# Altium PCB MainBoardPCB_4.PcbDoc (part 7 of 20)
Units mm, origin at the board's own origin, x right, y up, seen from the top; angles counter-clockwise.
Board outline 333.63 x 349.38 mm, 16 copper layers (L1, L2 (GND), L3 (Sign), L4 (GND), L5 (Sign), L6 (PWR/GND), L7(PWR/GND), L8 (Plane_GND), L9 (PWR/GND), L10 (PWR/GND), L11 (PWR/GND), L12 (Sign), L13 (GND), L14 (Sign), L15 (GND), L16), stack 2.502 mm thick; 2205 components, 1648 nets, 8314 pads, 3172 vias.
Unrouted connection lines stored in the file: 5141.
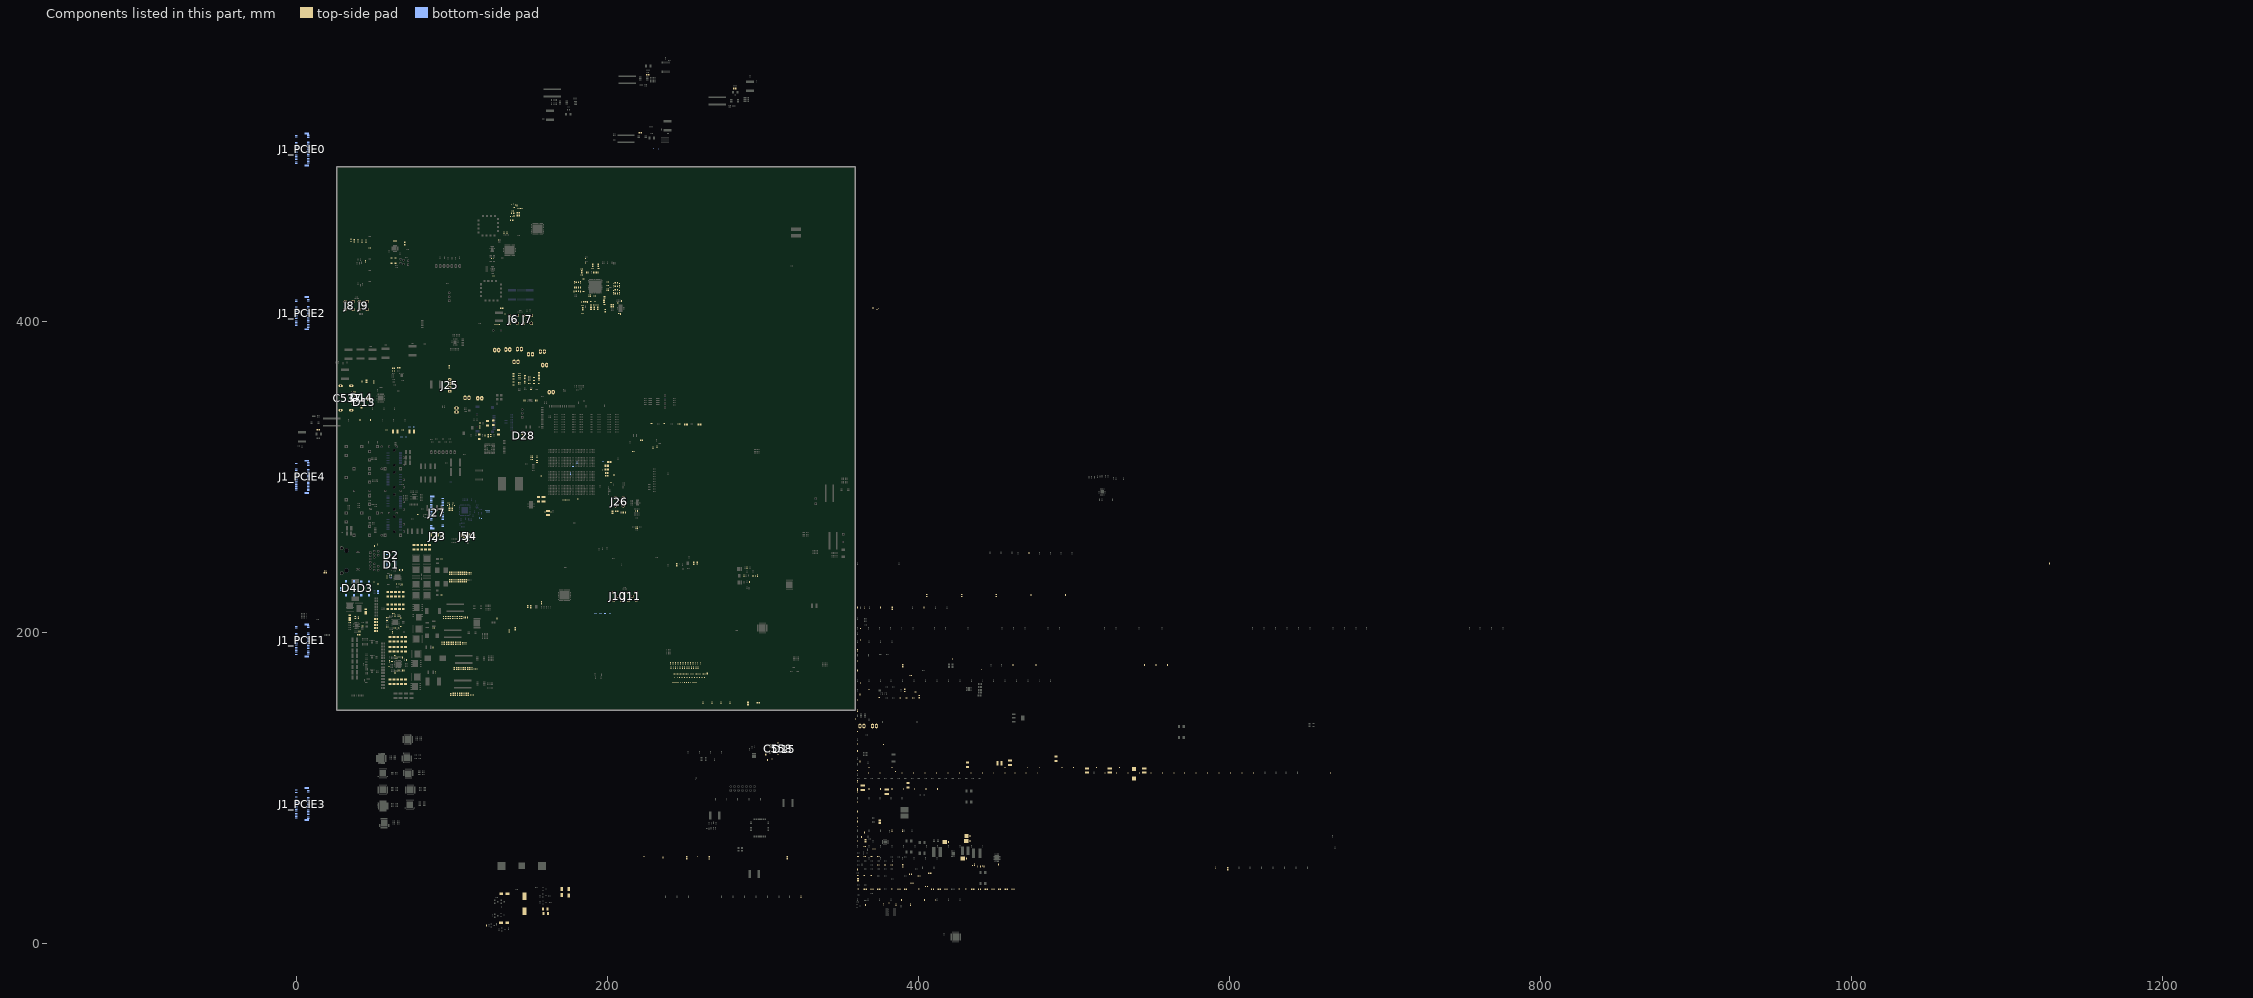
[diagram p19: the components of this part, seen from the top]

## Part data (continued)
C46: library part Capacitor, "Multilayer Ceramic Capacitors MLCC - SMD/SMT 200pF 50V NPO 5%", Case Code (Imperial)=0402, Case Code (Metric)=1005, Dielectric=C0G, Manufacturer=Yageo, Manufacturer Part Number=CC0402JRNPO9BN201, Max Operating Temperature=125°C, Min Operating Temperature=-55°C, Supplier Part Number 1=311-1664-1-ND, Tolerance=5%, Voltage Rating=50V
C53 C54 C326 C327 C328 C329: library part Capacitor, Case/Package=0402, Dielectric=X5R, Dielectric Material=Ceramic, Manufacturer=KEMET, Manufacturer Part Number=C0402C105K9PACTU, Max Operating Temperature=85°C, Min Operating Temperature=-55°C, Package Quantity=1, Supplier Part Number 1=399-4873-6-ND, Tolerance=10%, Voltage=6.3V
C55 C56 C57 C59 C60 C61 C65 C66 C71 C72 C73 C84 C85 C94 C95: library part Capacitor, "SMT Capacitor", Part Number=GRM033R61C104ME84D, Supplier Part Number 1=490-9986-1-ND
C58 C62 C69 C74 C87 C98: library part Capacitor, "SMT Capacitor", Part Number=AMK105CBJ106MV-F, Supplier Part Number 1=587-3237-1-ND
C63 C64 C67 C70 C75 C76 C77 C81 C82 C83 C88 C89 C90 C91 C92 C93 C96 C99 C100 C103 C104 C107 C108 C124 C125 C141 C142 C145 C146 C162 C163 C179 C336 C337 C338 C578 C579 C583 C590: library part Capacitor, "CAP CER 0.1UF 50V X5R 0402", Case Code (Imperial)=0402, Case Code (Metric)=1005, Dielectric=X5R, Dielectric Material=Ceramic, Manufacturer=Murata, Manufacturer Part Number=GRM155R61H104KE14D, Max Operating Temperature=85°C, Min Operating Temperature=-55°C, Package Quantity=10000, Supplier Part Number 1=490-10697-1-ND, Tolerance=10%, Voltage=50V
C68 C86 C97 C111 C112 C113 C114 C115 C116 C117 C118 C119 C120 C121 C122 C123 C149 C150 C151 C152 C153 C154 C155 C156 C157 C158 C159 C160 C161 C166 C167 C168 C169 C170 C171 C172 C173 C174 C175 C176 C177 C178 C333 C344 C573 C577: library part Capacitor, "Cap Ceramic 0.01uF 16V X5R 10% SMD 0201 85C Paper T/R", Case Code (Imperial)=0201, Case Code (Metric)=0603, Dielectric=X5R, Manufacturer=Yageo, Manufacturer Part Number=CC0201KRX5R7BB103, Max Operating Temperature=85°C, Min Operating Temperature=-55°C, Supplier Part Number 1=311-1596-1-ND, Tolerance=10%, Voltage Rating=16V
C78 C79 C80 C101 C102 C105 C106 C109 C110 C126 C127 C143 C144 C147 C148 C164 C165 C180 C591: library part Capacitor, "CAP CER 10UF 10V X5R 0402", Case Code (Imperial)=0402, Case Code (Metric)=1005, Manufacturer=Samsung, Manufacturer Part Number=CL05A106MP8NUB8, Max Operating Temperature=85°C, Min Operating Temperature=-55°C, Supplier Part Number 1=1276-6830-1-ND, Tolerance=20%, Voltage Rating=10V
C128 C129 C130 C131 C132 C133 C134 C135 C136 C137 C138 C139 C140 C181 C182 C183 C184 C185 C186 C187 C188 C189 C190 C191 C192 C193 C194 C195 C196 C197 C198 C199 C200 C201 C202 C203 C204 C205 C206: library part Capacitor, "CAP CER 1UF 10V X5R 0402", Case Code (Imperial)=0402, Case Code (Metric)=1005, Dielectric=X5R, Manufacturer=Yageo, Manufacturer Part Number=CC0402KRX5R6BB105, Max Operating Temperature=85°C, Min Operating Temperature=-55°C, Package Quantity=1, Supplier Part Number 1=311-1439-1-ND, Tolerance=10%, Voltage Rating=10V
C207 C209: library part Capacitor, Case/Package=0402, Case Code (Metric)=1005, Dielectric=X7R, Manufacturer=Murata, Manufacturer Part Number=GRM155R71E104KE14J, Max Operating Temperature=125°C, Min Operating Temperature=-55°C, Package Quantity=50000, Supplier Part Number 1=490-14603-1-ND, Tolerance=10%, Voltage Rating=25V
C208 C210: library part Capacitor, Case/Package=1210, Case Code (Metric)=3225, Dielectric=X5R, Manufacturer=Samsung, Manufacturer Part Number=CL32A226KAJNNNE, Max Operating Temperature=85°C, Min Operating Temperature=-55°C, Package Quantity=1, Supplier Part Number 1=1276-1101-1-ND, Tolerance=10%, Voltage=25V
C223 C228 C233 C238 C247 C252 C257 C262 C550 C552 C554 C568 C569 C570: library part Capacitor, "0402 10 V 4.7 uF ±20% Tolerance X5R Multilayer Ceramic Chip Capacitor", Case Code (Imperial)=0402, Case Code (Metric)=1005, Manufacturer=Murata, Manufacturer Part Number=GRM155R61A475MEAAD, Max Operating Temperature=85°C, Min Operating Temperature=-55°C, Supplier Part Number 1=490-14306-1-ND, Tolerance=20%, Voltage Rating=10V
C224 C225 C229 C230 C234 C235 C239 C240 C248 C249 C253 C254 C258 C259 C263 C264: library part Capacitor, "Cap Ceramic 0.47uF 10V X5R 10% SMD 0402 85C Paper T/R", Case Code (Imperial)=0402, Case Code (Metric)=1005, Dielectric=X5R, Manufacturer=Samsung, Manufacturer Part Number=CL05A474KP5NNNC, Max Operating Temperature=85°C, Min Operating Temperature=-55°C, Supplier Part Number 1=1276-1173-1-ND, Tolerance=10%, Voltage Rating=10V
C226 C227 C231 C232 C236 C237 C241 C242 C250 C251 C255 C256 C260 C261 C265 C266: library part Capacitor, "KEMET - C0402C683K4RACTU - CAP, 0.068µF, 16V, 10%, X7R, 0402", Case Code (Imperial)=0402, Case Code (Metric)=1005, Dielectric=X7R, Dielectric Material=Ceramic, Manufacturer=KEMET, Manufacturer Part Number=C0402C683K4RACTU, Max Operating Temperature=125°C, Min Operating Temperature=-55°C, Package Quantity=1, Supplier Part Number 1=399-4904-1-ND, Tolerance=10%, Voltage=16V
C267 C269 C271 C274 C279 C281 C283 C286 C291 C293 C295 C298: library part Capacitor, "CAP CER 0.1UF 16V X5R 0201", Case Code (Metric)=0603, Case/Package=0201, Dielectric=X5R, Manufacturer=Murata, Manufacturer Part Number=GRM033R61C104ME84D, Max Operating Temperature=85°C, Min Operating Temperature=-55°C, Package Quantity=15000, Supplier Part Number 1=490-9986-1-ND, Tolerance=20%, Voltage Rating=16V
C268 C270 C272 C275 C280 C282 C284 C287 C292 C294 C296 C299 C629: library part Capacitor, "CAP CER 0.1UF 16V X5R 0201", Case Code (Imperial)=0201, Case Code (Metric)=0603, Dielectric=X5R, Manufacturer=Murata, Manufacturer Part Number=GRM033R61C104ME84D, Max Operating Temperature=85°C, Min Operating Temperature=-55°C, Package Quantity=15000, Supplier Part Number 1=490-9986-1-ND, Tolerance=20%, Voltage Rating=16V
C273 C276 C277 C278 C285 C288 C289 C290 C297 C300 C301 C302: library part Capacitor, "CAP CER 10000PF 16V X7R 0201", Dielectric=X7R, Manufacturer=Murata, Manufacturer Part Number=GRM033R71C103KE14D, Supplier Part Number 1=490-14453-1-ND, Tolerance=10%, Voltage Rating (DC)=16V
C303_I2C_Bridge C303_I2C_Bridge_2 C303_I2C_Bridge_3 C406 C418 C447 C459 C517 C519 C521 C545 C546 C547 C566_5V_to_3V3_for_FTDI C623 C649 C651 C653 C654 C677 C715 C716 C717 C718: library part Capacitor, Case/Package=0402, Case Code (Metric)=1005, Dielectric=X5R, Insulation Resistance=10GR, Manufacturer=Yageo, Manufacturer Part Number=CC0402KRX5R6BB104, Max Operating Temperature=85°C, Min Operating Temperature=-55°C, Package Quantity=1, Supplier Part Number 1=311-1336-1-ND, Tolerance=10%, Voltage Rating=10V
C304 C305 C306 C307: library part Capacitor, "SMT Capacitor", Part Number=CL10A475KO8NNNC, Supplier Part Number 1=1276-1784-2-ND
C308 C354 C355 C606 C607 C610 C611 C613 C614 C615 C617 C618 C619 C620 C621 C622: library part Capacitor, "SMT Capacitor", Part Number=CL10A475KQ8NNNC, Supplier Part Number 1=1276-1045-1-ND
C309_U_Pomiar_pradu_napiecia_1 C309_U_Pomiar_pradu_napiecia_2 C309_U_Pomiar_pradu_napiecia_3 C309_U_Pomiar_pradu_napiecia_4 C309_U_Pomiar_pradu_napiecia_5 C309_U_Pomiar_pradu_napiecia_6 C309_U_Pomiar_pradu_napiecia_7 C309_U_Pomiar_pradu_napiecia_8 C309_U_Pomiar_pradu_napiecia_9 C309_U_Pomiar_pradu_napiecia_10 C309_U_Pomiar_pradu_napiecia_11 C310 C585 C711 C712: library part Capacitor, "CAP CER 0.1UF 50V X5R 0402", Case/Package=0402, Case Code (Metric)=1005, Dielectric=X5R, Dielectric Material=Ceramic, Manufacturer=Murata, Manufacturer Part Number=GRM155R61H104KE14D, Max Operating Temperature=85°C, Min Operating Temperature=-55°C, Package Quantity=10000, Supplier Part Number 1=490-10697-1-ND, Tolerance=10%, Voltage=50V
C311_I2C_Expander1 C311_I2C_Expander2 C311_I2C_Expander3 C311_I2C_Expander? C311_I2C_Expander_10 C311_I2C_Expander_11 C311_I2C_Expander_12 C311_I2C_Expander_13 C311_I2C_Expander_14 C311_I2C_Expander_15 C311_I2C_Expander_16 C544 C700 C720 C721 C722 C723: library part Capacitor, "MURATA - GRT155R61E105KE01D - SMD Multilayer Ceramic Capacitor, 1 µF, 25 V, 0402 [1005 Metric], ± 10%, X5R, GRT Series - SMD Multilayer Ceramic Capacitor, 1 µF, 25 V, 0402 [1005 Metric], ± 10%, X5R, GRT Series", Case/Package=0402, Case Code (Metric)=1005, Dielectric=X5R, Manufacturer=Murata, Manufacturer Part Number=GRT155R61E105KE01D, Max Operating Temperature=85°C, Min Operating Temperature=-55°C, Ratings=AEC-Q200, Supplier Part Number 1=490-12263-1-ND, Tolerance=10%, Voltage Rating=25V
C320: library part Capacitor, Case/Package=0402, Case Code (Metric)=1005, Dielectric=X7R, Dielectric Material=Ceramic, Manufacturer=KEMET, Manufacturer Part Number=C0402C103K8RACAUTO, Max Operating Temperature=125°C, Min Operating Temperature=-55°C, Package Quantity=1, Ratings=AEC-Q200, Supplier Part Number 1=399-6827-1-ND, Tolerance=10%, Voltage Rating=10V
C321: library part Capacitor, Case/Package=0603, Case Code (Metric)=1608, Manufacturer="Wurth Electronics", Manufacturer Part Number=885012006016, Max Operating Temperature=125°C, Min Operating Temperature=-55°C, Supplier Part Number 1=732-7759-1-ND, Tolerance=5%, Voltage Rating=10V
C322 C323: library part Capacitor, Case/Package=0402, Case Code (Metric)=1005, Dielectric=C0G, Dielectric Material=Ceramic, Manufacturer=KEMET, Manufacturer Part Number=C0402C270K5GACTU, Max Operating Temperature=125°C, Min Operating Temperature=-55°C, Package Quantity=1, Supplier Part Number 1=399-8960-1-ND, Tolerance=10%, Voltage Rating=50V
C324: library part Capacitor, Case/Package=0805, Case Code (Metric)=2012, Manufacturer=Samsung, Manufacturer Part Number=CL21A106KQCLRNC, Max Operating Temperature=85°C, Min Operating Temperature=-55°C, Package Quantity=1, Supplier Part Number 1=1276-2405-1-ND, Tolerance=10%, Voltage Rating=6.3V
C325 C330 C334 C335 C342 C343 C593 C594: library part Capacitor, Case Code (Imperial)=0402, Case Code (Metric)=1005, Dielectric=X7R, Dielectric Material=Ceramic, Insulation Resistance=10GR, Manufacturer=Murata, Manufacturer Part Number=GRM155R71C104KA88D, Max Operating Temperature=125°C, Min Operating Temperature=-55°C, Package Quantity=1, Supplier Part Number 1=490-3261-6-ND, Tolerance=10%, Voltage=16V
C331 C332 C395 C398 C408 C420 C436 C439 C449 C461 C522 C538 C559 C733 C734: library part Capacitor, Case/Package=0402, Case Code (Metric)=1005, Dielectric=X5R, Manufacturer=Yageo, Manufacturer Part Number=CC0402KRX5R6BB105, Max Operating Temperature=85°C, Min Operating Temperature=-55°C, Package Quantity=1, Supplier Part Number 1=311-1439-1-ND, Tolerance=10%, Voltage Rating=10V
C339: library part Capacitor, Case Code (Imperial)=0805, Case Code (Metric)=2012, Manufacturer=Samsung, Manufacturer Part Number=CL21A106KQCLRNC, Max Operating Temperature=85°C, Min Operating Temperature=-55°C, Package Quantity=1, Supplier Part Number 1=1276-2405-1-ND, Tolerance=10%, Voltage Rating=6.3V
C341 C479 C482 C483 C484 C540 C541 C542 C543 C728 C729 C732 C735 C790: library part Capacitor, Case/Package=0402, Case Code (Metric)=1005, Dielectric=X7R, Dielectric Material=Ceramic, Insulation Resistance=10GR, Manufacturer=Murata, Manufacturer Part Number=GRM155R71C104KA88D, Max Operating Temperature=125°C, Min Operating Temperature=-55°C, Package Quantity=1, Supplier Part Number 1=490-3261-6-ND, Tolerance=10%, Voltage=16V
C345 C349 C535 C536: library part Capacitor, Case Code (Imperial)=0402, Case Code (Metric)=1005, Dielectric=C0G, Manufacturer="Kyocera AVX", Manufacturer Part Number=04025A220JAT2A, Max Operating Temperature=125°C, Min Operating Temperature=-55°C, Package Quantity=1, Supplier Part Number 1=478-1074-1-ND, Temperature Coefficient=30ppm/°C, Tolerance=5%, Voltage=50V
C346 C350 C713: library part Capacitor, Case Code (Imperial)=0402, Case Code (Metric)=1005, Dielectric=X5R, Manufacturer=Multicomp, Manufacturer Part Number=MC0402X104K160CT, Max Operating Temperature=85°C, Min Operating Temperature=-55°C, Supplier Part Number 1=2310529, Tolerance=10%, Voltage Rating=16V
C347 C348 C352 C353 C391 C392 C396 C397 C432 C433 C437 C438: library part Capacitor, Case/Package=1206, Case Code (Metric)=3216, Dielectric=X7R, Manufacturer 1=Murata, Manufacturer Part Number 1=GRM31CR71E106MA12L, Max Operating Temperature=125°C, Min Operating Temperature=-55°C, Package Quantity=1, Supplier Part Number 1=490-6519-1-ND, Tolerance=20%, Voltage=25V
C351 C356 C361 C379 C680: library part Capacitor, Case Code (Imperial)=0402, Case Code (Metric)=1005, Dielectric=X5R, Manufacturer=Yageo, Manufacturer Part Number=CC0402KRX5R6BB105, Max Operating Temperature=85°C, Min Operating Temperature=-55°C, Package Quantity=1, Supplier Part Number 1=311-1439-1-ND, Tolerance=10%, Voltage Rating=10V
C357 C399 C440: library part Capacitor, Case/Package=0402, Case Code (Metric)=1005, Dielectric=X5R, Dielectric Material=Ceramic, Manufacturer 1=KEMET, Manufacturer Part Number 1=C0402C104M8PACTU, Max Operating Temperature=85°C, Min Operating Temperature=-55°C, Package Quantity=1, Supplier Part Number 1=399-7764-1-ND, Tolerance=20%, Voltage=10V
C358: library part Capacitor, "Cap Ceramic 1uF 10V X5R 10% SMD 0603 85C Paper T/R", Case Code (Imperial)=0603, Case Code (Metric)=1608, Dielectric=X5R, Manufacturer=Samsung, Manufacturer Part Number=CL10A105KP8NNNC, Max Operating Temperature=85°C, Min Operating Temperature=-55°C, Package Quantity=1, Supplier Part Number 1=1276-1182-1-ND, Tolerance=10%, Voltage=10V
C360 C378: library part Capacitor, Case Code (Imperial)=0402, Case Code (Metric)=1005, Dielectric=X5R, Manufacturer=Samsung, Manufacturer Part Number=CL05A474KP5NNNC, Max Operating Temperature=85°C, Min Operating Temperature=-55°C, Supplier Part Number 1=1276-1173-1-ND, Tolerance=10%, Voltage Rating=10V
C362 C380 C563_U_5V_to_3V31 C563_U_5V_to_3V32 C563_U_5V_to_3V33 C564_U_5V_to_3V31 C564_U_5V_to_3V32 C564_U_5V_to_3V33 C565_U_5V_to_3V31 C565_U_5V_to_3V32 C565_U_5V_to_3V33: library part Capacitor, Case Code (Imperial)=0603, Case Code (Metric)=1608, Dielectric=X5R, Manufacturer=Samsung, Manufacturer Part Number=CL10A475KP8NNNC, Max Operating Temperature=85°C, Min Operating Temperature=-55°C, Package Quantity=1, Supplier Part Number 1=1276-1044-1-ND, Tolerance=10%, Voltage Rating=10V
C363 C365 C367 C369 C381 C383 C385 C387 C572 C576 C598 C631: library part Capacitor, Case Code (Imperial)=0603, Case Code (Metric)=1608, Dielectric=X5R, Manufacturer=Murata, Manufacturer Part Number=GRM188R61A106KE69D, Max Operating Temperature=85°C, Min Operating Temperature=-55°C, Supplier Part Number 1=490-10474-1-ND, Tolerance=10%, Voltage=10V
C364 C366 C368 C370 C382 C384 C386 C388: library part Capacitor, Case Code (Imperial)=0603, Case Code (Metric)=1608, Dielectric=X5R, Manufacturer=Murata, Manufacturer Part Number=GRM188R61A226ME15D, Max Operating Temperature=85°C, Min Operating Temperature=-55°C, Package Quantity=4000, Supplier Part Number 1=490-10476-1-ND, Tolerance=20%, Voltage Rating=10V
C371 C372 C373 C374 C375 C376: library part Capacitor, "Cap Ceramic 10uF 25V X5R 10% SMD 1206 85C Embossed T/R", Case Code (Imperial)=1206, Case Code (Metric)=3216, Dielectric=X5R, Manufacturer=Samsung, Manufacturer Part Number=CL31A106KAHNNNE, Max Operating Temperature=85°C, Min Operating Temperature=-55°C, Supplier Part Number 1=1276-1075-1-ND, Tolerance=10%, Voltage=25V
C389 C393 C430 C434: library part Capacitor, Case/Package=0402, Case Code (Metric)=1005, Dielectric=C0G, Manufacturer="Kyocera AVX", Manufacturer Part Number=04025A220JAT2A, Max Operating Temperature=125°C, Min Operating Temperature=-55°C, Package Quantity=1, Supplier Part Number 1=478-1074-1-ND, Temperature Coefficient=30ppm/°C, Tolerance=5%, Voltage=50V
C390 C394 C431 C435 C658 C660 C662 C665 C666 C667 C668 C669 C670 C671 C673 C783 C785 C787 C789 C791 C792: library part Capacitor, Case/Package=0402, Case Code (Metric)=1005, Dielectric=X5R, Manufacturer=Multicomp, Manufacturer Part Number=MC0402X104K160CT, Max Operating Temperature=85°C, Min Operating Temperature=-55°C, Supplier Part Number 1=2310529, Tolerance=10%, Voltage Rating=16V
C400 C401 C402 C403 C404 C405 C441 C442 C443 C444 C445 C446: library part Capacitor, "Cap Ceramic 10uF 25V X5R 10% SMD 1206 85C Embossed T/R", Case/Package=1206, Case Code (Metric)=3216, Dielectric=X5R, Manufacturer=Samsung, Manufacturer Part Number=CL31A106KAHNNNE, Max Operating Temperature=85°C, Min Operating Temperature=-55°C, Supplier Part Number 1=1276-1075-1-ND, Tolerance=10%, Voltage=25V
C407 C419 C448 C460: library part Capacitor, Case/Package=0402, Case Code (Metric)=1005, Dielectric=X5R, Manufacturer=Samsung, Manufacturer Part Number=CL05A474KP5NNNC, Max Operating Temperature=85°C, Min Operating Temperature=-55°C, Supplier Part Number 1=1276-1173-1-ND, Tolerance=10%, Voltage Rating=10V
C409 C421 C450 C462 C515 C516 C523 C524 C539 C560 C563_5V_to_3V3_for_FTDI C564_5V_to_3V3_for_FTDI C565_5V_to_3V3_for_FTDI C659 C661: library part Capacitor, Case/Package=0603, Case Code (Metric)=1608, Dielectric=X5R, Manufacturer=Samsung, Manufacturer Part Number=CL10A475KP8NNNC, Max Operating Temperature=85°C, Min Operating Temperature=-55°C, Package Quantity=1, Supplier Part Number 1=1276-1044-1-ND, Tolerance=10%, Voltage Rating=10V
C410 C412 C414 C416 C422 C424 C426 C428 C451 C453 C455 C457 C463 C465 C467 C469 C705 C709: library part Capacitor, Case/Package=0603, Case Code (Metric)=1608, Dielectric=X5R, Manufacturer=Murata, Manufacturer Part Number=GRM188R61A106KE69D, Max Operating Temperature=85°C, Min Operating Temperature=-55°C, Supplier Part Number 1=490-10474-1-ND, Tolerance=10%, Voltage=10V
C411 C413 C415 C417 C423 C425 C427 C429 C452 C454 C456 C458 C464 C466 C468 C470: library part Capacitor, Case/Package=0603, Case Code (Metric)=1608, Dielectric=X5R, Manufacturer=Murata, Manufacturer Part Number=GRM188R61A226ME15D, Max Operating Temperature=85°C, Min Operating Temperature=-55°C, Package Quantity=4000, Supplier Part Number 1=490-10476-1-ND, Tolerance=20%, Voltage Rating=10V
C471 C472 C473 C474: library part Capacitor, Case/Package=0402, Case Code (Metric)=1005, Dielectric=X5R, Manufacturer 1=Yageo, Manufacturer Part Number 1=CC0402KRX5R8BB104, Max Operating Temperature=85°C, Min Operating Temperature=-55°C, Supplier Part Number 1=311-1697-1-ND, Tolerance=10%, Voltage Rating=25V
C480 C481: library part Capacitor, "Multilayer Ceramic Capacitors MLCC - SMD/SMT 16V 27pF C0G 0402 10% Tol", Case/Package=0402, Case Code (Metric)=1005, Dielectric=C0G, Manufacturer="Kyocera AVX", Manufacturer Part Number=0402YA270KAT2A, Max Operating Temperature=125°C, Min Operating Temperature=-55°C, Package Quantity=10000, Supplier Part Number 1=66M2135, Tolerance=10%, Voltage Rating=16V
C485 C486 C491 C492 C493 C499 C500 C505 C506 C507 C508: library part Capacitor, Case/Package=0402, Dielectric=X5R, Dielectric Material=Ceramic, Manufacturer 1=KEMET, Manufacturer Part Number 1=C0402C105K9PACTU, Max Operating Temperature=85°C, Min Operating Temperature=-55°C, Package Quantity=1, Supplier Part Number 1=399-4873-6-ND, Tolerance=10%, Voltage=6.3V
C487 C488 C494 C495 C496 C501 C502 C509 C510 C511 C512 C561 C562: library part Capacitor, Case/Package=0402, Case Code (Metric)=1005, Dielectric=X5R, Dielectric Material=Ceramic, Manufacturer 1=KEMET, Manufacturer Part Number 1=C0402C104M9PACTU, Max Operating Temperature=85°C, Min Operating Temperature=-55°C, Package Quantity=1, Supplier Part Number 1=399-8944-1-ND, Tolerance=20%, Voltage Rating=6.3V
C489 C497 C503 C513: library part Capacitor, Case/Package=0402, Case Code (Metric)=1005, Manufacturer 1=Murata, Manufacturer Part Number 1=GRJ155R60J106ME11D, Max Operating Temperature=85°C, Min Operating Temperature=-55°C, Supplier Part Number 1=490-13211-1-ND, Tolerance=20%, Voltage Rating=6.3V
C490 C498 C504 C514: library part Capacitor, Case/Package=0402, Case Code (Metric)=1005, Dielectric=X5R, Dielectric Material=Ceramic, Manufacturer 1=KEMET, Manufacturer Part Number 1=C0402C103K4PACTU, Max Operating Temperature=85°C, Min Operating Temperature=-55°C, Supplier Part Number 1=399-11930-1-ND, Tolerance=10%, Voltage Rating=16V
C518 C520 C567_5V_to_3V3_for_FTDI C586 C587: library part Capacitor, "CAP CER 2.2UF 6.3V X5R 0402", Case/Package=0402, Case Code (Metric)=1005, Dielectric=X5R, Manufacturer="Taiyo Yuden", Manufacturer Part Number=JMK105BJ225KV-F, Max Operating Temperature=85°C, Min Operating Temperature=-55°C, Package Quantity=10000, Supplier Part Number 1=587-5867-1-ND, Tolerance=10%, Voltage Rating=6.3V
C525 C526 C527 C528 C529 C530: library part Capacitor, Case Code (Imperial)=0402, Case Code (Metric)=1005, Dielectric=X7R, Dielectric Material=Ceramic, Manufacturer=KEMET, Manufacturer Part Number=C0402C103K8RACAUTO, Max Operating Temperature=125°C, Min Operating Temperature=-55°C, Package Quantity=1, Ratings=AEC-Q200, Supplier Part Number 1=399-6827-1-ND, Tolerance=10%, Voltage Rating=10V
C531 C532 C533 C534 C588 C589 C592: library part Capacitor, "Cap Ceramic 0.1uF 25V X7R 20% SMD 0402 125C Paper T/R", Case Code (Imperial)=0402, Case Code (Metric)=1005, Dielectric=X7R, Manufacturer=Murata, Manufacturer Part Number=GRM155R71E104ME14D, Max Operating Temperature=125°C, Min Operating Temperature=-55°C, Package Quantity=10000, Supplier Part Number 1=490-13341-1-ND, Tolerance=20%, Voltage Rating=25V
C537: "WR-COM USB 3.0 Horizontal Type A", Manufacturer="Würth Elektronik eiSos GmbH", partNo=692121130100
C548: library part Capacitor, Case/Package=0402, Case Code (Metric)=1005, Dielectric=C0G, Manufacturer=Yageo, Manufacturer Part Number=CC0402JRNPO9BN110, Max Operating Temperature=125°C, Min Operating Temperature=-55°C, Package Quantity=1, Supplier Part Number 1=311-1015-1-ND, Tolerance=5%, Voltage Rating=50V
C549: library part Capacitor, Case/Package=0402, Case Code (Metric)=1005, Dielectric=X7R, Dielectric Material=Ceramic, Insulation Resistance=100GR, Manufacturer=Yageo, Manufacturer Part Number=CC0402KRX7R9BB221, Max Operating Temperature=125°C, Min Operating Temperature=-55°C, Package Quantity=1, Supplier Part Number 1=311-1035-1-ND, Tolerance=10%, Voltage Rating=50V
C551 C553 C555: library part Capacitor, "CAP CER 10UF 6.3V X5R 0402", Case/Package=0402, Case Code (Metric)=1005, Manufacturer=Murata, Manufacturer Part Number=GRJ155R60J106ME11D, Max Operating Temperature=85°C, Min Operating Temperature=-55°C, Supplier Part Number 1=490-13211-1-ND, Tolerance=20%, Voltage Rating=6.3V
C558: "WR-COM_USB_Micro Type B_Vertical_THT", Manufacturer="Würth Elektronik eiSos GmbH", partNo=614105150721
C571 C719: library part Capacitor, "CAP CER 1000PF 25V X5R 0201", Case/Package=0201, Dielectric=X5R, Manufacturer=Murata, Manufacturer Part Number=GRM033R61E102KA01D, Max Operating Temperature=85°C, Min Operating Temperature=-55°C, Supplier Part Number 1=490-14452-1-ND, Tolerance=10%, Voltage Rating (DC)=25V
C595 C596 C695 C696 C697 C698 C699: library part Capacitor, Dielectric=X5R, Manufacturer=Murata, Manufacturer Part Number=GRM21BR61H106KE43L, Supplier Part Number 1=490-18663-1-ND, Tolerance=10%, Voltage Rating (DC)=50V
C597: library part Capacitor, "MURATA - GRT155R61E105KE01D - SMD Multilayer Ceramic Capacitor, 1 µF, 25 V, 0402 [1005 Metric], ± 10%, X5R, GRT Series - SMD Multilayer Ceramic Capacitor, 1 µF, 25 V, 0402 [1005 Metric], ± 10%, X5R, GRT Series", Case Code (Imperial)=0402, Case Code (Metric)=1005, Dielectric=X5R, Manufacturer=Murata, Manufacturer Part Number=GRT155R61E105KE01D, Max Operating Temperature=85°C, Min Operating Temperature=-55°C, Ratings=AEC-Q200, Supplier Part Number 1=490-12263-1-ND, Tolerance=10%, Voltage Rating=25V
C603 C612: library part Capacitor, Case/Package=0201, Case Code (Metric)=0603, Dielectric=C0G, Manufacturer=Murata, Manufacturer Part Number=GRM0335C1H430GA01D, Max Operating Temperature=125°C, Min Operating Temperature=-55°C, Package Quantity=15000, Supplier Part Number 1=490-14799-1-ND, Tolerance=2%, Voltage Rating=50V
C604: library part Capacitor, "SMT Capacitor", Part Number=CL05A105MQ5NNNC, Supplier Part Number 1=1276-1235-6-ND
C605 C616: library part Capacitor, Case/Package=0201, Case Code (Metric)=0603, Dielectric=C0G, Manufacturer=Murata, Manufacturer Part Number=GRM0335C1E101JA01D, Max Operating Temperature=125°C, Min Operating Temperature=-55°C, Package Quantity=15000, Supplier Part Number 1=490-3160-1-ND, Tolerance=5%, Voltage=25V
C609: "Supercapacitors / Ultracapacitors 0.22F 5.5volts SMD Super Capacitor", Capacitance=220mF, Case/Package=Radial, ESR (Equivalent Series Resistance)=25R, Leakage Current=330uA, Manufacturer=KEMET, Max Operating Temperature=70°C, Min Operating Temperature=-25°C, Package Quantity=500, Supplier Part Number 1=18X4838, Tolerance=80%, Voltage=5.5V
C624 C625 C626: library part Capacitor, Case/Package=0201, Case Code (Metric)=0603, Dielectric=X5R, Manufacturer=Yageo, Manufacturer Part Number=CC0201KRX5R7BB103, Max Operating Temperature=85°C, Min Operating Temperature=-55°C, Supplier Part Number 1=311-1596-1-ND, Tolerance=10%, Voltage Rating=16V
C627: library part Capacitor, "CAP CER 0.1UF 16V X5R 0201", Case/Package=0201, Case Code (Metric)=0603, Dielectric=X5R, Manufacturer=Murata, Manufacturer Part Number=GRM033R61C104ME84D, Max Operating Temperature=85°C, Min Operating Temperature=-55°C, Package Quantity=15000, Supplier Part Number 1=490-9986-1-ND, Tolerance=20%, Voltage Rating=16V
C628: library part Capacitor, "Multilayer Ceramic Capacitors MLCC - SMD/SMT 470nF 6.3V X5R 10%", Case/Package=0402, Case Code (Metric)=1005, Dielectric=X5R, Manufacturer=Yageo, Manufacturer Part Number=CC0402KRX5R5BB474, Max Operating Temperature=85°C, Min Operating Temperature=-55°C, Supplier Part Number 1=311-1684-1-ND, Tolerance=10%, Voltage Rating=6.3V
C630 C632: library part Capacitor, "Multilayer Ceramic Capacitors MLCC - SMD/SMT 470nF 6.3V X5R 10%", Case Code (Imperial)=0402, Case Code (Metric)=1005, Dielectric=X5R, Manufacturer=Yageo, Manufacturer Part Number=CC0402KRX5R5BB474, Max Operating Temperature=85°C, Min Operating Temperature=-55°C, Supplier Part Number 1=311-1684-1-ND, Tolerance=10%, Voltage Rating=6.3V
C633 C636: library part Capacitor, Case/Package=0402, Case Code (Metric)=1005, Dielectric=U2J, Manufacturer=Murata, Manufacturer Part Number=GRM1557U1A302JA01D, Max Operating Temperature=125°C, Min Operating Temperature=-55°C, Package Quantity=10000, Supplier Part Number 1=490-8243-1-ND, Tolerance=5%, Voltage Rating=10V
C634: library part Capacitor, Case/Package=0402, Case Code (Metric)=1005, Dielectric=X7R, Dielectric Material=Ceramic, Insulation Resistance=100GR, Manufacturer=Yageo, Manufacturer Part Number=CC0402KRX7R9BB331, Max Operating Temperature=125°C, Min Operating Temperature=-55°C, Package Quantity=1, Supplier Part Number 1=311-1027-1-ND, Tolerance=10%, Voltage Rating=50V
C635: library part Capacitor, Case/Package=0402, Case Code (Metric)=1005, Dielectric=X7R, Manufacturer=Yageo, Manufacturer Part Number=CC0402KRX7R9BB682, Max Operating Temperature=125°C, Min Operating Temperature=-55°C, Supplier Part Number 1=311-1726-1-ND, Tolerance=10%, Voltage=50V
C637 C638 C645 C646: library part Capacitor, "CAP CER 1200PF 50V X7R 0402", Case Code (Imperial)=0402, Case Code (Metric)=1005, Dielectric=X7R, Manufacturer=Yageo, Manufacturer Part Number=CC0402KRX7R9BB122, Max Operating Temperature=125°C, Min Operating Temperature=-55°C, Package Quantity=1, Supplier Part Number 1=311-1031-1-ND, Tolerance=10%, Voltage Rating=50V
C639 C640 C647 C648: library part Capacitor, Case/Package=0402, Case Code (Metric)=1005, Dielectric=X7R, Insulation Resistance=10GR, Manufacturer=Yageo, Manufacturer Part Number=CC0402KRX7R8BB473, Max Operating Temperature=125°C, Min Operating Temperature=-55°C, Supplier Part Number 1=311-1717-1-ND, Tolerance=10%, Voltage Rating=25V
C641: library part Capacitor, Case/Package=0402, Dielectric=X7R, Dielectric Material=Ceramic, Manufacturer=KEMET, Manufacturer Part Number=C0402C471K5RACTU, Max Operating Temperature=125°C, Min Operating Temperature=-55°C, Supplier Part Number 1=399-1025-1-ND, Tolerance=10%, Voltage=50V
C642: library part Capacitor, Case/Package=0402, Case Code (Metric)=1005, Dielectric=C0G, Manufacturer=Yageo, Manufacturer Part Number=CC0402JRNPO9BN560, Max Operating Temperature=125°C, Min Operating Temperature=-55°C, Package Quantity=1, Supplier Part Number 1=311-1022-1-ND, Tolerance=5%, Voltage Rating=50V
C643: library part Capacitor, Case/Package=0402, Case Code (Metric)=1005, Dielectric=X7R, Manufacturer=Yageo, Manufacturer Part Number=CC0402KRX7R7BB822, Max Operating Temperature=125°C, Min Operating Temperature=-55°C, Package Quantity=1, Supplier Part Number 1=311-1041-1-ND, Tolerance=10%, Voltage Rating=16V
C644: library part Capacitor, Case/Package=0402, Case Code (Metric)=1005, Dielectric=X7R, Manufacturer=Yageo, Manufacturer Part Number=CC0402KRX7R9BB821, Max Operating Temperature=125°C, Min Operating Temperature=-55°C, Package Quantity=10000, Supplier Part Number 1=311-1727-1-ND, Tolerance=10%, Voltage=50V
C650: library part Capacitor, Case/Package=0402, Case Code (Metric)=1005, Dielectric=C0G, Manufacturer=Yageo, Manufacturer Part Number=CC0402JRNPO9BN181, Max Operating Temperature=125°C, Min Operating Temperature=-55°C, Supplier Part Number 1=311-1663-1-ND, Tolerance=5%, Voltage Rating=50V
C652: library part Capacitor, Case/Package=0402, Case Code (Metric)=1005, Dielectric=X7R, Manufacturer=Yageo, Manufacturer Part Number=CC0402KRX7R7BB222, Max Operating Temperature=125°C, Min Operating Temperature=-55°C, Package Quantity=10000, Supplier Part Number 1=311-1707-1-ND, Tolerance=10%, Voltage Rating=16V
C655 C656 C657: library part Capacitor, Case/Package=0402, Case Code (Metric)=1005, Dielectric=X7R, Manufacturer=Yageo, Manufacturer Part Number=CC0402KRX7R8BB562, Max Operating Temperature=125°C, Min Operating Temperature=-55°C, Supplier Part Number 1=311-1718-1-ND, Tolerance=10%, Voltage Rating=25V
C663 C664: library part Capacitor, "KEMET - C0402C270J5GACTU - Multilayer Ceramic Capacitor, C Series, 27 pF, -  5%, C0G / NP0, 50 V, 0402 [1005 Metric] RoHS Compliant: Yes", Case/Package=0402, Case Code (Metric)=1005, Dielectric=C0G, Dielectric Material=Ceramic, Manufacturer=KEMET, Manufacturer Part Number=C0402C270J5GACTU, Max Operating Temperature=125°C, Min Operating Temperature=-55°C, Package Quantity=1, Supplier Part Number 1=399-1016-1-ND, Temperature Coefficient=30ppm/°C, Tolerance=5%, Voltage=50V
C674 C675 C676 C782 C784 C786 C788: library part Capacitor, "0402 10 V 4.7 uF ±20% Tolerance X5R Multilayer Ceramic Chip Capacitor", Case/Package=0402, Case Code (Metric)=1005, Manufacturer=Murata, Manufacturer Part Number=GRM155R61A475MEAAD, Max Operating Temperature=85°C, Min Operating Temperature=-55°C, Supplier Part Number 1=490-14306-1-ND, Tolerance=20%, Voltage Rating=10V
C678 C679: library part Capacitor, "Cap Ceramic 100uF 6.3V X6T 20% Pad SMD 1206 105C T/R", Case Code (Imperial)=1206, Case Code (Metric)=3216, Dielectric=X6T, Dielectric Material=Ceramic, Manufacturer=Murata, Manufacturer Part Number=GRM31CD80J107ME39L, Max Operating Temperature=105°C, Min Operating Temperature=-55°C, Package Quantity=2000, Supplier Part Number 1=490-10525-1-ND, Tolerance=20%, Voltage=6.3V
C693: library part Capacitor, "CAP CER 0.47UF 25V X5R 0402", Case/Package=0402, Case Code (Metric)=1005, Manufacturer=Murata, Manufacturer Part Number=GRT155R61E474KE01D, Max Operating Temperature=85°C, Min Operating Temperature=-55°C, Ratings=AEC-Q200, Supplier Part Number 1=490-12269-1-ND, Tolerance=10%, Voltage Rating=25V
C694: library part Capacitor, "0603 4.7 uF 35 V ±10% Tolerance X5R Multilayer Ceramic Chip Capacitor", Case/Package=0603, Case Code (Metric)=1608, Dielectric=X5R, Manufacturer=Murata, Manufacturer Part Number=GRM188R6YA475KE15D, Max Operating Temperature=85°C, Min Operating Temperature=-55°C, Package Quantity=4000, Supplier Part Number 1=490-7205-6-ND, Tolerance=10%, Voltage=35V
C701: library part Capacitor, "CAP, MLCC, X7R, 0.012UF, 16V, 0402; Product Range:C Series; Capacitance:0.012 F; Capacitance Tolerance: 10%; Dielectric Characteristic:X7R; Voltage Rating:16V; Ceramic Capacitor Case:0402 [1005 Metric]; Operating Temperature ;RoHS Compliant: Yes", Case/Package=0402, Case Code (Metric)=1005, Dielectric=X7R, Dielectric Material=Ceramic, Manufacturer=KEMET, Manufacturer Part Number=C0402C123K4RACTU, Max Operating Temperature=125°C, Min Operating Temperature=-55°C, Package Quantity=1, Supplier Part Number 1=399-4875-1-ND, Tolerance=10%, Voltage=16V
C702: library part Capacitor, "Ceramic Capacitor 36PF 50V, C0G, 5%, 0402, Full Reel", Case/Package=0402, Case Code (Metric)=1005, Dielectric=C0G, Manufacturer="Kyocera AVX", Manufacturer Part Number=04025A360JAT2A, Max Operating Temperature=125°C, Min Operating Temperature=-55°C, Package Quantity=10000, Supplier Part Number 1=478-10099-1-ND, Tolerance=5%, Voltage Rating=50V
C703: library part Capacitor, "Cap Ceramic 0.015uF 25V X7R 10% SMD 0402 125C Paper T/R", Case/Package=0402, Case Code (Metric)=1005, Dielectric=X7R, Manufacturer=Yageo, Manufacturer Part Number=CC0402KRX7R8BB153, Max Operating Temperature=125°C, Min Operating Temperature=-55°C, Supplier Part Number 1=311-1713-1-ND, Tolerance=10%, Voltage Rating=25V
C704: library part Capacitor, "Cap Ceramic 1uF 10V X5R 10% SMD 0603 85C Paper T/R", Case/Package=0603, Case Code (Metric)=1608, Dielectric=X5R, Manufacturer=Samsung, Manufacturer Part Number=CL10A105KP8NNNC, Max Operating Temperature=85°C, Min Operating Temperature=-55°C, Package Quantity=1, Supplier Part Number 1=1276-1182-1-ND, Tolerance=10%, Voltage=10V
C706 C710: library part Capacitor, "Cap Ceramic 0.01uF 16V X5R 10% SMD 0201 85C Paper T/R", Case/Package=0201, Case Code (Metric)=0603, Dielectric=X5R, Manufacturer=Yageo, Manufacturer Part Number=CC0201KRX5R7BB103, Max Operating Temperature=85°C, Min Operating Temperature=-55°C, Supplier Part Number 1=311-1596-1-ND, Tolerance=10%, Voltage Rating=16V
C707 C708: library part Capacitor, "CAP CER 10UF 25V X5R 0805", Case/Package=0805, Case Code (Metric)=2012, Dielectric=X5R, Dielectric Material=Ceramic, Manufacturer=KEMET, Manufacturer Part Number=C0805C106K3PACTU, Max Operating Temperature=85°C, Min Operating Temperature=-55°C, Supplier Part Number 1=399-11939-6-ND, Tolerance=10%, Voltage=25V
C714: library part Capacitor, "CAP CER 0.33UF 25V Y5V 0603", Case Code (Imperial)=0603, Case Code (Metric)=1608, Dielectric=Y5V, Dielectric Material=Ceramic, Manufacturer=KEMET, Manufacturer Part Number=C0603C334Z3VACTU, Max Operating Temperature=85°C, Min Operating Temperature=-30°C, Package Quantity=1, Supplier Part Number 1=399-1292-1-ND, Tolerance=80%, Voltage Rating=25V
C724 C725 C726 C727: library part Capacitor, Case/Package=0201, Case Code (Metric)=0603, Dielectric=X7R, Manufacturer=Yageo, Manufacturer Part Number=CC0201KRX7R7BB103, Max Operating Temperature=125°C, Min Operating Temperature=-55°C, Package Quantity=1, Supplier Part Number 1=311-1404-1-ND, Tolerance=10%, Voltage Rating=16V
C730: library part Capacitor, Case/Package=0402, Dielectric=X7R, Dielectric Material=Ceramic, Insulation Resistance=10GR, Manufacturer=Murata, Manufacturer Part Number=GRM155R71C104KA88D, Max Operating Temperature=125°C, Min Operating Temperature=-55°C, Package Quantity=1, Supplier Part Number 1=490-3261-6-ND, Tolerance=10%, Voltage=16V
C731: library part Capacitor, Case/Package=0402, Case Code (Metric)=1005, Dielectric=X5R, Dielectric Material=Ceramic, Manufacturer=TDK, Manufacturer Part Number=C1005X5R1C225K050BC, Max Operating Temperature=85°C, Min Operating Temperature=-55°C, Package Quantity=1, Supplier Part Number 1=445-9085-1-ND, Tolerance=10%, Voltage Rating=16V
C736 C737: library part Capacitor, Case/Package=0201, Case Code (Metric)=0603, Manufacturer=Murata, Manufacturer Part Number=GRM0335C1E9R0CA01D, Max Operating Temperature=125°C, Min Operating Temperature=-55°C, Package Quantity=15000, Supplier Part Number 1=490-16718-1-ND, Voltage Rating=25V
C738: "CAP TANT POLY 680UF 6.3V 2917", Capacitance=680uF, Case/Package=2917, Case Code (Metric)=7343, ESR (Equivalent Series Resistance)=18mR, Leakage Current=428.4uA, Manufacturer=Panasonic, Max Operating Temperature=105°C, Min Operating Temperature=-55°C, Package Quantity=1, Ripple Current=3.5A, Supplier Part Number 1=P16633CT-ND, Tolerance=20%, Voltage=6.3V
C739 C742 C747 C751 C753 C757 C760 C762 C764: library part Capacitor, Case/Package=1210, Case Code (Metric)=3225, Dielectric=X7U, Manufacturer=Murata, Manufacturer Part Number=GRM32EE70G107ME19L, Max Operating Temperature=125°C, Min Operating Temperature=-55°C, Package Quantity=1, Supplier Part Number 1=490-6534-1-ND, Tolerance=20%, Voltage Rating=4V
C740 C741 C743 C745 C746 C748 C750 C752 C754 C755 C758 C761 C763 C765: library part Capacitor, Case/Package=0402, Case Code (Metric)=1005, Manufacturer=Murata, Manufacturer Part Number=GRM155R61A475MEAAD, Max Operating Temperature=85°C, Min Operating Temperature=-55°C, Supplier Part Number 1=490-14306-1-ND, Tolerance=20%, Voltage Rating=10V
C744 C749 C756 C759: library part Capacitor, Case/Package=1206, Case Code (Metric)=3216, Dielectric=X5R, Dielectric Material=Ceramic, Manufacturer=KEMET, Manufacturer Part Number=C1206C476M8PACTU, Max Operating Temperature=85°C, Min Operating Temperature=-55°C, Package Quantity=1, Supplier Part Number 1=399-5508-1-ND, Tolerance=20%, Voltage=10V
C781: library part Capacitor, "CAP CER 4.7UF 25V X5R 0805", Case/Package=0805, Case Code (Metric)=2012, Dielectric=X5R, Manufacturer=Murata, Manufacturer Part Number=GRM219R61E475KA73D, Max Operating Temperature=85°C, Min Operating Temperature=-55°C, Package Quantity=4000, Supplier Part Number 1=490-12753-1-ND, Tolerance=10%, Voltage Rating=25V
D1 D2: library part SLVU2.8-4BTG, "ESD Suppressor TVS ±30KV 8-Pin SOIC T/R", Breakdown Voltage=3V, Capacitance=2.5pF, Case/Package=SOIC, Clamping Voltage=15V, Leakage Current=1uA, Manufacturer=Littelfuse, Max Operating Temperature=85°C, Max Power Dissipation=600W, Min Operating Temperature=-40°C, Operating Supply Voltage=2.8V, Package Quantity=2500, Peak Pulse Current=40A, Power Line Protection=No, Supplier Part Number 1=F4206CT-ND
D3 D4: "DIODE BRIDGE 100V 2A SDIP", Case/Package=SMD/SMT, Forward Current=2A, Forward Voltage=1.1V, Manufacturer="ON Semiconductor / Fairchild", Max Forward Surge Current (Ifsm)=85A, Max Operating Temperature=150°C, Max Repetitive Reverse Voltage (Vrrm)=100V, Min Operating Temperature=-55°C, Package Quantity=1500, Peak Reverse Current=3uA, Reverse Voltage (DC)=70V, Supplier Part Number 1=DF01S2CT-ND
D5 D6 D7 D8 D9 D10: "LED,  LTST-C190GKT", Case/Package=0603, Case Code (Metric)=1608, Color=Green, Forward Current=30mA, Forward Voltage=2.1V, Lens Color=Colorless, Manufacturer 1="Vishay Lite-On", Max Operating Temperature=85°C, Min Operating Temperature=-55°C, Package Quantity=1, Power Dissipation=100mW, Reverse Voltage=5V, Supplier Part Number 1=160-1183-1-ND, Test Current=10mA, Voltage=2V
D11 D12: "DIODE SCHOTTKY 30V 200MA SOD123", Average Rectified Current=200mA, Capacitance=10pF, Case/Package=SOD-123-2, Forward Voltage=350mV, Manufacturer="ON Semiconductor", Max Forward Surge Current (Ifsm)=600mA, Max Operating Temperature=125°C, Max Repetitive Reverse Voltage (Vrrm)=30V, Max Reverse Leakage Current=2uA, Min Operating Temperature=-55°C, Package Quantity=3000, Power Dissipation=400mW, Supplier Part Number 1=BAT54T1GOSCT-ND
D13 D15: "TVS DIODE 5.5V 8V SOT3", Breakdown Voltage=9V, Capacitance=0.8pF, Case/Package=SOT, Clamping Voltage=8V, Manufacturer="Texas Instruments", Max Operating Temperature=85°C, Min Operating Temperature=-40°C, Package Quantity=1, Peak Pulse Current=1A, Peak Pulse Power=45W, Power Line Protection=Yes, Reverse Standoff Voltage=5.5V, Supplier Part Number 1=296-25509-1-ND, Test Current=1mA
D14: "TVS DIODE 5.5V 8V 10SON", Breakdown Voltage=7V, Capacitance=0.8pF, Clamping Voltage=8V, Current Rating=5A, Manufacturer="Texas Instruments", Max Operating Temperature=85°C, Min Operating Temperature=-40°C, Package Quantity=1, Peak Pulse Current=1A, Peak Pulse Power=45W, Power Line Protection=Yes, Reverse Standoff Voltage=5.5V, Supplier Part Number 1=296-28063-1-ND
D16 D17 D18 D19: library part MBRM140T1G, Supplier Part Number 1=MBRM140T3GOSCT-ND
D20 D21 D22 D23: "DIODE GEN PURP 1KV 1A SMA", Average Rectified Current=1A, Capacitance=10pF, Case/Package=SMA, Forward Voltage="Vf {} 1.1V", Manufacturer=Diodes, Max Forward Surge Current (Ifsm)=30A, Max Operating Temperature=150°C, Max Repetitive Reverse Voltage (Vrrm)=1kV, Min Operating Temperature=-65°C, Package Quantity=5000, Peak Reverse Current=5uA, Supplier Part Number 1=S1M-FDICT-ND
D26 D27: "DIODE SCHOTTKY 100V POWERDI123", Average Rectified Current=1A, Capacitance=36pF, Forward Voltage=770mV, Manufacturer=Diodes, Max Forward Surge Current (Ifsm)=40A, Max Operating Temperature=175°C, Max Repetitive Reverse Voltage (Vrrm)=100V, Min Operating Temperature=-55°C, Package Quantity=3000, Peak Non-Repetitive Surge Current=50A, Peak Reverse Current=1uA, Supplier Part Number 1=DFLS1100DICT-ND
D28: "DIODE ARRAY SCHOTTKY 40V SOT23", Average Rectified Current=200mA, Capacitance=5pF, Case/Package=SOT-23, Forward Voltage=1V, Manufacturer=MCC, Max Forward Surge Current (Ifsm)=600mA, Max Operating Temperature=125°C, Max Repetitive Reverse Voltage (Vrrm)=40V, Max Reverse Leakage Current=200nA, Min Operating Temperature=-55°C, Package Quantity=3000, Power Dissipation=200mW, Supplier Part Number 1=BAS40-04TPMSCT-ND
FB1_PCIE0 FB1_PCIE1 FB1_PCIE2 FB1_PCIE3 FB1_PCIE4 FB23 FB25: "SMT Ferrite Chip", Case/Package=0603, Case Code (Metric)=1608, Current Rating=1.7A, DC Resistance (DCR)=80mR, Manufacturer=TDK, Manufacturer Part Number=MPZ1608S331ATA00, Package Quantity=1, Supplier Part Number 1=445-5221-1-ND, Tolerance=25%
FB2 FB3 FB4 FB5 FB6 FB7 FB35: library part "Ferrite Chip", "SMT Ferrite Chip", Part Number=CIS10P221NC, Supplier Part Number 1=1276-6350-1-ND
FB8 FB9 FB10 FB11 FB12 FB13 FB14 FB15 FB16 FB17 FB18 FB19 FB20 FB21 FB22 FB36 FB37: library part Ferrite, "FERRITE BEAD 220 OHM 0603 1LN", Case Code (Imperial)=0603, Case Code (Metric)=1608, Current Rating=2.5A, DC Resistance (DCR)=40mR, Manufacturer=Murata, Manufacturer Part Number=BLM18SG221TN1D, Max Operating Temperature=125°C, Min Operating Temperature=-55°C, Package Quantity=1, Supplier Part Number 1=490-5225-1-ND, Test Frequency=100MHz, Tolerance=25%
FB24: "SMT Ferrite Chip", Case Code (Imperial)=0603, Case Code (Metric)=1608, Current Rating=1.7A, DC Resistance (DCR)=80mR, Manufacturer=TDK, Manufacturer Part Number=MPZ1608S331ATA00, Package Quantity=1, Supplier Part Number 1=445-5221-1-ND, Tolerance=25%
FB26 FB27 FB31 FB32 FB43 FB44: library part Ferrite, "FERRITE BEAD 220 OHM 0603 1LN", Case/Package=0603, Case Code (Metric)=1608, Current Rating=2.5A, DC Resistance (DCR)=40mR, Manufacturer=Murata, Manufacturer Part Number=BLM18SG221TN1D, Max Operating Temperature=125°C, Min Operating Temperature=-55°C, Package Quantity=1, Supplier Part Number 1=490-5225-1-ND, Test Frequency=100MHz, Tolerance=25%
FB28 FB29: library part Ferrite, "FERRITE BEAD 220 OHM 0603 1LN", Case/Package=0603, Case Code (Metric)=1608, DC Resistance (DCR)=50mR, Manufacturer=TDK, Manufacturer Part Number=MPZ1608S221ATD25, Max Current Rating=2.2A, Max Operating Temperature=125°C, Min Operating Temperature=-55°C, Package Quantity=4000, Ratings=AEC-Q200, Supplier Part Number 1=445-172893-1-ND, Test Frequency=100MHz, Tolerance=25%
FB33: library part Ferrite, "Ferrite SMD 2 A 0.05 Ohm, BLM18EG121SN1D, Murata", Case Code (Imperial)=0603, Case Code (Metric)=1608, Current Rating=2A, DC Resistance (DCR)=40mR, Frequency=100MHz, Manufacturer=Murata, Manufacturer Part Number=BLM18EG121SN1D, Max Operating Temperature=125°C, Min Operating Temperature=-55°C, Package Quantity=1, Supplier Part Number 1=490-3991-1-ND, Tolerance=25%
FB34: library part Ferrite, "Ferrite Beads Power Chip 330Ohm 25% 100MHz 800mA 210mOhm DCR 0603 Automotive T/R", Case Code (Imperial)=0603, Case Code (Metric)=1608, DC Resistance (DCR)=210mR, Frequency=100MHz, Manufacturer="Taiyo Yuden", Manufacturer Part Number=FBMH1608HL331-T, Max Current Rating=800mA, Max DC Current=600mA, Max Operating Temperature=125°C, Min Operating Temperature=-40°C, Package Quantity=1, Supplier Part Number 1=587-1734-1-ND, Tolerance=25%
FB38 FB39 FB40 FB41: library part Ferrite, "FERRITE BEAD 600 OHM 0805 1LN", Case Code (Imperial)=0805, Case Code (Metric)=2012, Current Rating=500mA, DC Resistance (DCR)=300mR, Frequency=100MHz, Manufacturer=Laird, Manufacturer Part Number=HZ0805E601R-10, Max Operating Temperature=125°C, Min Operating Temperature=-40°C, Package Quantity=1, Supplier Part Number 1=240-2399-1-ND
FB42: library part Ferrite, "Ind Chip Bead 120Ohm 25% 100MHz Ferrite 3A 0603 Paper T/R", Case Code (Imperial)=0603, Case Code (Metric)=1608, Current Rating=3A, DC Resistance (DCR)=25mR, Frequency=100MHz, Manufacturer=Murata, Manufacturer Part Number=BLM18SG121TN1D, Max Operating Temperature=125°C, Min Operating Temperature=-55°C, Package Quantity=1, Supplier Part Number 1=1515752, Tolerance=25%
FB45: library part Ferrite, "Ferrite SMD 2 A 0.05 Ohm, BLM18EG121SN1D, Murata", Case/Package=0603, Case Code (Metric)=1608, Current Rating=2A, DC Resistance (DCR)=40mR, Frequency=100MHz, Manufacturer=Murata, Manufacturer Part Number=BLM18EG121SN1D, Max Operating Temperature=125°C, Min Operating Temperature=-55°C, Package Quantity=1, Supplier Part Number 1=490-3991-1-ND, Tolerance=25%
J1_PCIE0 J1_PCIE1 J1_PCIE2 J1_PCIE3 J1_PCIE4: library part 1-2199230-6, "CONN EDGE DUAL FMALE 67POS 0.020", Contact Current Rating=500mA, Housing Color=Black, Manufacturer 1="TE Connectivity", Package Quantity=1, Supplier Part Number 1=A118046CT-ND
J2 J3 J4 J5: "Ultra Miniature Coaxial Connector Jack, 60 V, 50 Ohm, -40 to 90 degC, RoHS, Tape and Reel", Maximum Frequency="6 GHz", Operating Temperature Range="- 40 C to + 90 C", Supplier Part Number 1=62X0488
J6 J7 J8 J9 J10 J11 J26: "SMA Connector, Pitch 5.08 mm, 1 Position, Height 9.5 mm, Tail Length 4 mm, -65 to 165 degC, RoHS, Bulk", Frequency Max=3GHz, Supplier Part Number 1=78M7270
J12 J13 J15 J16 J17 J19 J20 J21 J22 J23 J24 J29 J30: library part "2 Pin"
J25: library part "4 Pin"
J27: library part 1-2199230-6_CHINA, "CONN EDGE DUAL FMALE 67POS 0.020", Contact Current Rating=500mA, Housing Color=Black, Manufacturer 1="TE Connectivity", Manufacturer Part Number 1=1-2199230-6, Package Quantity=1, Supplier Part Number 1=A118046CT-ND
